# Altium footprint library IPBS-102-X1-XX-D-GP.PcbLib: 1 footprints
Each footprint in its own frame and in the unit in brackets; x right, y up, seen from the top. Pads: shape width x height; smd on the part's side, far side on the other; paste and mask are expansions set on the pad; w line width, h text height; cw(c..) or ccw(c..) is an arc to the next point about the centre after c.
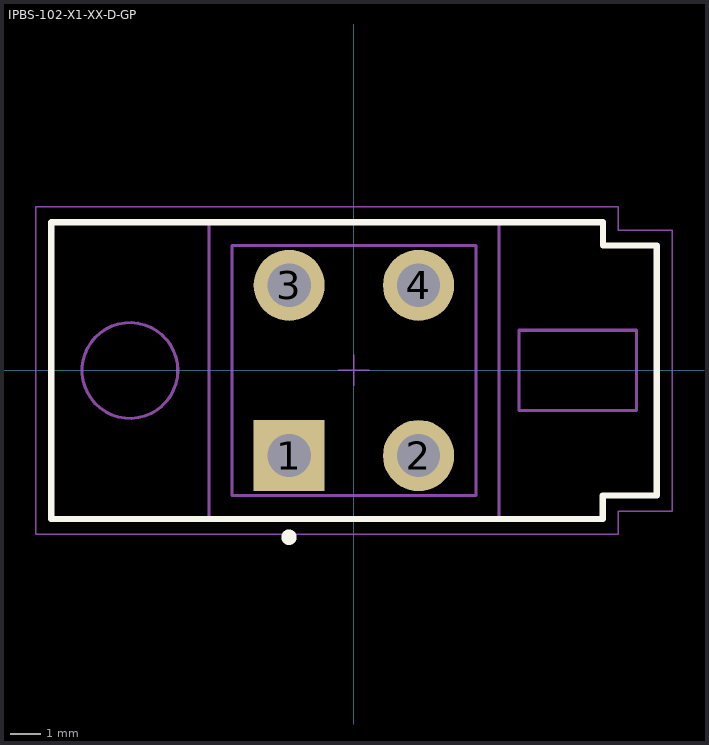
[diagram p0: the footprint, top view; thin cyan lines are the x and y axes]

## IPBS-102-X1-XX-D-GP [mm] "4.19mm pitch, power-mate socket; double row"
height 13.84
pads (4):
  rect 2.3x2.3 / inner round 2.3 / far side rect 2.3x2.3 hole 1.4 mask+0: 1(-2.095,-2.755)
  round 2.3 hole 1.4 mask+0: 2(2.095,-2.755) 3(-2.095,2.755) 4(2.095,2.755)
Top Overlay:
  circle w0.25: c-2.1,-5.4 r0.125
  lines w0.2: -9.795,-4.805 -9.795,4.795 8.065,4.795 8.065,4.045 9.805,4.045 9.805,-4.05 8.055,-4.05 8.055,-4.805 -9.795,-4.805
Mechanical 12:
  lines w0.001: -9.795,-4.805 -9.795,4.795 8.065,4.795 8.065,4.045 9.805,4.045 9.805,-4.05 8.055,-4.05 8.055,-4.805 -9.795,-4.805
Mechanical 13:
  circle w0.1: c-7.25,0 r1.55
  lines w0.1: -4.695,-4.805 -4.695,4.795 ; 4.705,-4.805 4.705,4.795 ; -9.795,-4.805 -9.795,4.795 8.065,4.795 8.065,4.045 9.805,4.045 9.805,-4.05 8.055,-4.05 8.055,-4.805 -9.795,-4.805 ; -3.95,-4.05 -3.95,4.05 3.955,4.05 3.955,-4.05 -3.95,-4.05 ; 5.35,-1.3 5.35,1.3 9.15,1.3 9.15,-1.3 5.35,-1.3
  text ".Designator" at 0.254,0.254 h1.52
Mechanical 15:
  lines w0.05: -0.5,0 0.5,0 ; 0,-0.5 0,0.5 ; -10.295,-5.305 -10.295,5.295 8.555,5.295 8.555,4.545 10.305,4.545 10.305,-4.555 8.555,-4.555 8.555,-5.305 -10.295,-5.305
